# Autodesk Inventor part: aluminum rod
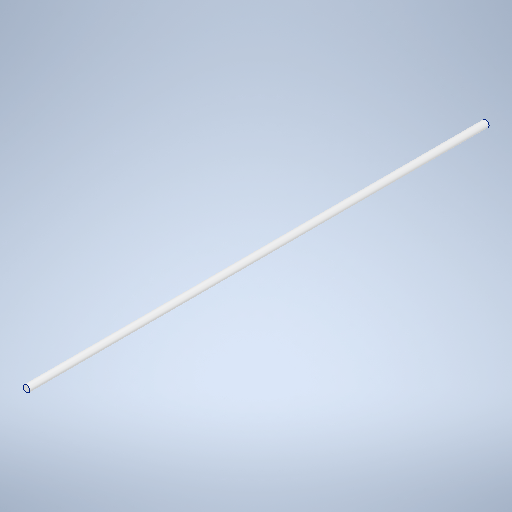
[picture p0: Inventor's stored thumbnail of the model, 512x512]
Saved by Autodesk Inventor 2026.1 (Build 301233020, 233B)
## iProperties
Created: 2026-10
Part Number: aluminum rod
Material: Aluminum 6061
Document SubType Name: Modeling
Designer: hp
Density: 2.7 g/cm^3
Appearance: Aluminum - Flat
Author: hp
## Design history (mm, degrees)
sketch "Sketch1"
  geometry: C1 r 5 at (0, 0); 1 further point
  constraints: 1 centre point, 1 coincident
  dimensions: "d0" = 10 diameter of C1
extrude "Extrusion1" new body sketch "Sketch1" distance "d1" = 670; taper "d2" = 0 deg
body "Solid1"
